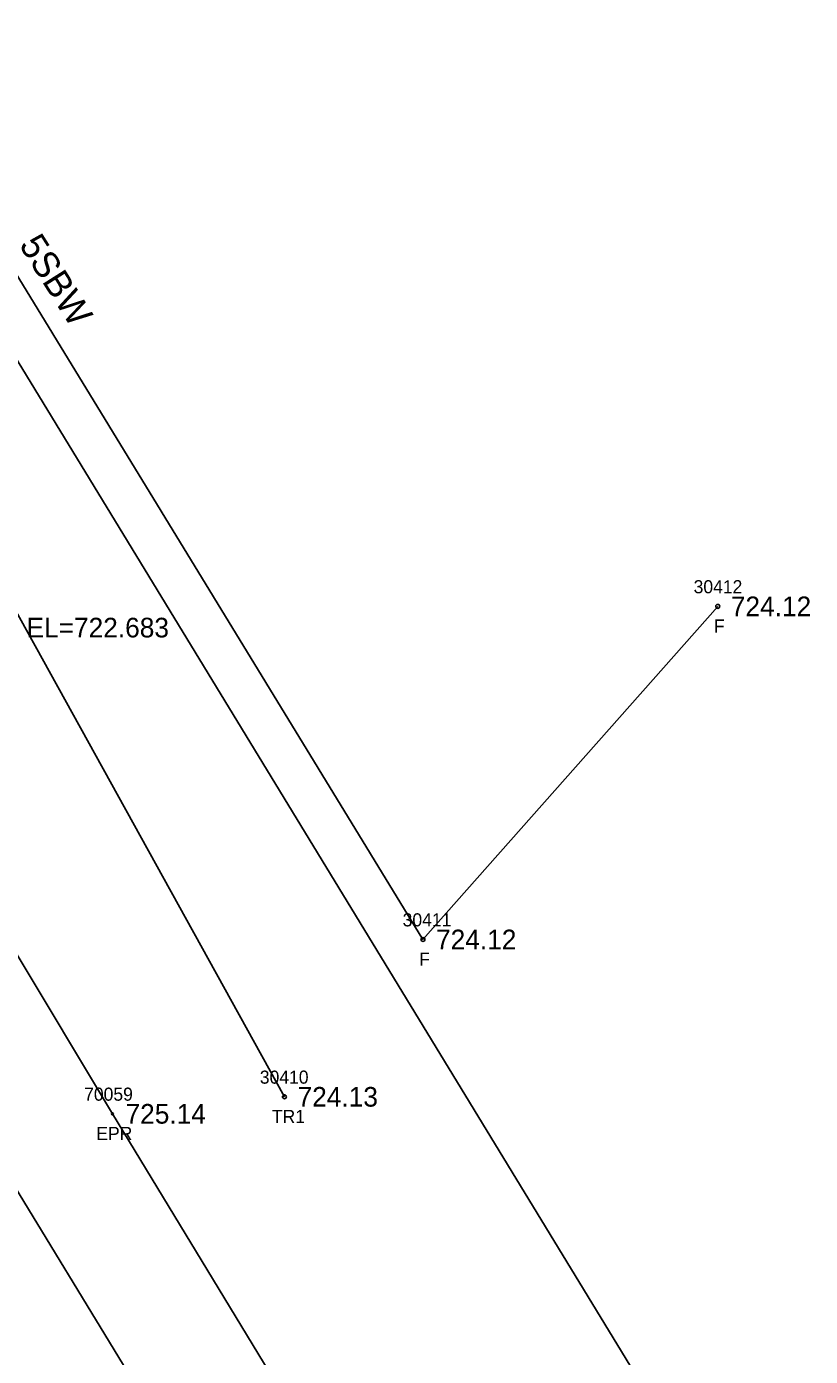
# Model space of a CAD drawing. Extents: x 1375131 to 1378678, y 999028 to 1004053.
# Drawn here: x 1377680.1 to 1377739.9, y 1001130.3 to 1001231.8 of the extents above; entities that cross this region are included whole.
import ezdxf

# ---------------------------------------------------------------- set-up
doc = ezdxf.new("R2010")
doc.units = 0
for name, color, linetype in [('RD_EX_Fence_Other', 7, 'Continuous'), ('RD_EX_Fence_Other_txCode', 7, 'Continuous'), ('RD_EX_Road', 7, 'Continuous'), ('RD_EX_Road_txCode', 7, 'Continuous'), ('RD_EX_RW', 7, 'Continuous'), ('RD_EX_TX_Fence_Other_ELEV', 7, 'Continuous'), ('RD_EX_TX_H2O_ELEV', 7, 'Continuous'), ('RD_EX_TX_Road_ELEV', 7, 'Continuous'), ('RD_EX_TX_VEG_ELEV', 7, 'Continuous'), ('RD_EX_VEG', 7, 'Continuous'), ('RD_EX_VEG_txCode', 7, 'Continuous'), ('RD_HC_Cl', 7, 'Continuous'), ('RD_SMD_Locator', 7, 'Continuous'), ('RD_TX_Misc2', 7, 'Continuous')]:
    doc.layers.add(name, color=color, linetype=linetype)

msp = doc.modelspace()

# ---------------------------------------------------------------- linework, layer by layer
at = {"layer": 'RD_EX_Fence_Other'}
msp.add_lwpolyline([(1377597.87, 1001348.47), (1377630.37, 1001294.19), (1377658.14, 1001247.6), (1377710.37, 1001162.09), (1377732.87, 1001187.52)], dxfattribs=at)
at = {"layer": 'RD_EX_Road'}
msp.add_lwpolyline([(1377899.67, 1000800.29), (1377898.72, 1000801.84), (1377870.31, 1000849.94), (1377847.28, 1000887.89), (1377815.15, 1000940.58), (1377781.51, 1000995.26), (1377748.62, 1001049.21), (1377716.58, 1001099.53), (1377686.67, 1001148.78), (1377656.47, 1001199.11), (1377629.54, 1001244.18), (1377599.89, 1001292.67), (1377570.87, 1001341.43), (1377539.83, 1001392.47), (1377511.01, 1001440.31), (1377480.72, 1001490), (1377449.73, 1001541.49), (1377420.9, 1001591.95), (1377390.45, 1001644.41)], dxfattribs=at)
at = {"layer": 'RD_EX_RW'}
msp.add_line((1377592.75, 1001348.44), (1377983.57, 1000707.36), dxfattribs=at)
at = {"layer": 'RD_EX_VEG'}
msp.add_lwpolyline([(1377699.8, 1001150.08), (1377647.34, 1001244.96), (1377619.03, 1001291.88), (1377568.9, 1001377.2)], dxfattribs=at)
at = {"layer": 'RD_HC_Cl'}
msp.add_line((1377564.57, 1001331.26), (1377955.4, 1000690.18), dxfattribs=at)
at = {"layer": 'RD_SMD_Locator'}
for centre, radius in [((1377732.87, 1001187.52), 0.15), ((1377710.37, 1001162.09), 0.15), ((1377699.8, 1001150.08), 0.15), ((1377686.67, 1001148.78), 0.075)]:
    msp.add_circle(centre, radius, dxfattribs=at)

# ---------------------------------------------------------------- texts
at = {"layer": 'RD_EX_Fence_Other_txCode'}
for s, p in [('30412', (1377731.03, 1001188.52)), ('F', (1377732.58, 1001185.52)), ('30411', (1377708.82, 1001163.09)), ('F', (1377710.08, 1001160.09))]:
    msp.add_text(s, height=1, dxfattribs=at).set_placement(p)
at = {"layer": 'RD_EX_Road_txCode'}
for s, p in [('70059', (1377684.51, 1001149.78)), ('EPR', (1377685.44, 1001146.78))]:
    msp.add_text(s, height=1, dxfattribs=at).set_placement(p)
at = {"layer": 'RD_EX_TX_Fence_Other_ELEV'}
for p in [(1377733.87, 1001186.77), (1377711.37, 1001161.34)]:
    msp.add_text('724.12', height=1.5, dxfattribs=at).set_placement(p)
at = {"layer": 'RD_EX_TX_H2O_ELEV'}
msp.add_text('EL=722.683', height=1.5, dxfattribs=at).set_placement((1377680.11, 1001185.15))
at = {"layer": 'RD_EX_TX_Road_ELEV'}
msp.add_text('725.14', height=1.5, dxfattribs=at).set_placement((1377687.67, 1001148.03))
at = {"layer": 'RD_EX_TX_VEG_ELEV'}
msp.add_text('724.13', height=1.5, dxfattribs=at).set_placement((1377700.8, 1001149.33))
at = {"layer": 'RD_EX_VEG_txCode'}
for s, p in [('30410', (1377697.92, 1001151.08)), ('TR1', (1377698.84, 1001148.08))]:
    msp.add_text(s, height=1, dxfattribs=at).set_placement(p)
at = {"layer": 'RD_TX_Misc2'}
msp.add_text('5SBW', height=2, rotation=302.3586, dxfattribs=at).set_placement((1377679.5, 1001215.11))

doc.saveas('drawing.dxf')
